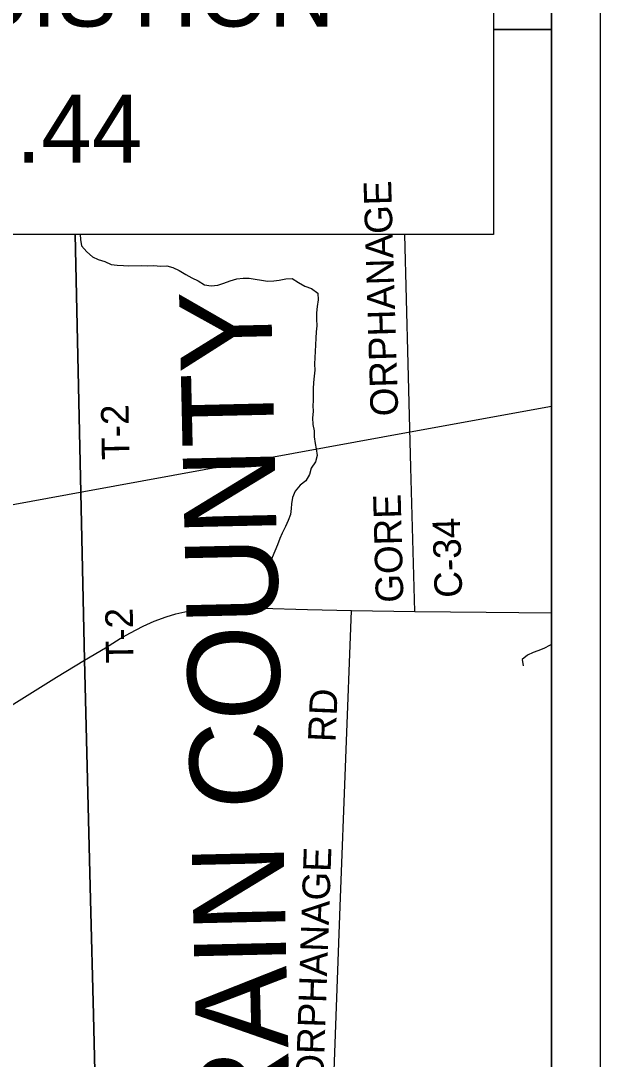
# Model space of a CAD drawing. Extents: x 0 to 34, y 0 to 22.
# Drawn here: x 7.808 to 9, y 17.578 to 19.717 of the extents above; entities that cross this region are included whole.
import ezdxf

# ---------------------------------------------------------------- set-up
doc = ezdxf.new("R2010")
doc.units = 0
for name, color, linetype in [('GM_X_Corporation', 7, 'Continuous'), ('GM_X_County_Road', 7, 'Continuous'), ('GM_X_County_Road_Text', 7, 'Continuous'), ('GM_X_County_Text', 7, 'Continuous'), ('GM_X_Minor_River', 7, 'Continuous'), ('GM_X_Rail_Line', 7, 'Continuous'), ('GM_X_Township_Road', 7, 'Continuous'), ('GM_X_Township_Road_Text', 7, 'Continuous'), ('GM_X_US_Route', 7, 'Continuous'), ('SH_Data', 7, 'Continuous'), ('SH_Text', 7, 'Continuous')]:
    doc.layers.add(name, color=color, linetype=linetype)

msp = doc.modelspace()

# ---------------------------------------------------------------- linework, layer by layer
at = {"layer": 'GM_X_Corporation'}
for points in [[(8.7801, 19.7002), (8.9, 19.6997), (8.9, 20.9), (7.8853, 20.9), (7.8855, 20.8777), (7.8865, 20.8322), (7.8862, 20.7899), (7.8881, 20.7568), (7.8881, 20.7393), (7.8896, 20.6817), (7.8919, 20.5951), (7.8945, 20.502), (7.9008, 20.2877), (7.9013, 20.2705), (7.9044, 19.994), (8.7801, 19.994)], [(7.9196, 19.2769), (7.9387, 18.4008), (7.951, 17.9078), (7.9575, 17.6697), (7.9659, 17.2939), (7.973, 17.0583), (7.9733, 17.0489), (7.9799, 16.8298), (7.992, 16.4534), (8.0153, 15.2273), (8.0262, 14.6555), (8.0297, 14.4963), (8.2922, 14.4944), (8.9, 14.4898), (8.9, 19.6997), (8.7801, 19.7002), (8.7801, 19.2769)]]:
    msp.add_lwpolyline(points, close=True, dxfattribs=at)
for points in [[(8.9, 14.1), (8.9, 20.9)], [(8.0153, 15.2273), (7.992, 16.4534), (7.9799, 16.8298), (7.9733, 17.0489), (7.973, 17.0583), (7.9659, 17.2939), (7.9575, 17.6697), (7.951, 17.9078), (7.9387, 18.4008), (7.9196, 19.2769), (6.5603, 19.2769), (6.5603, 19.994)], [(8.0153, 15.2273), (7.992, 16.4534), (7.9799, 16.8298), (7.9733, 17.0489), (7.973, 17.0583), (7.9659, 17.2939), (7.9575, 17.6697), (7.951, 17.9078), (7.9387, 18.4008), (7.9196, 19.2769), (6.5603, 19.2769), (6.5603, 19.994)], [(8.7801, 19.994), (8.7801, 19.2769), (7.9196, 19.2769), (7.9387, 18.4008), (7.951, 17.9078), (7.9575, 17.6697), (7.9659, 17.2939), (7.973, 17.0583), (7.9733, 17.0489), (7.9799, 16.8298), (7.992, 16.4534), (8.0153, 15.2273)]]:
    msp.add_lwpolyline(points, dxfattribs=at)
at = {"layer": 'GM_X_County_Road'}
for p, q in [((8.7801, 19.6997), (8.9, 19.6992)), ((8.4882, 18.5028), (8.6184, 18.5005))]:
    msp.add_line(p, q, dxfattribs=at)
for points in [[(8.6184, 18.5005), (8.6101, 18.7975), (8.6049, 19.0107), (8.598, 19.2769)], [(8.435, 17.0471), (8.4437, 17.3104), (8.465, 17.8934), (8.4882, 18.5028)]]:
    msp.add_lwpolyline(points, dxfattribs=at)
at = {"layer": 'GM_X_Minor_River'}
for points in [[(7.9299, 19.2769), (7.9303, 19.2665), (7.9327, 19.2536), (7.9431, 19.2412), (7.955, 19.2314), (7.9669, 19.2259), (7.9802, 19.2218), (7.9932, 19.2155), (8.0062, 19.2142), (8.0191, 19.2132), (8.0287, 19.2129), (8.0557, 19.2132), (8.0686, 19.2126), (8.0815, 19.2131), (8.0952, 19.2122), (8.1082, 19.2123), (8.1207, 19.209), (8.1337, 19.2031), (8.1472, 19.1949), (8.1594, 19.1878), (8.1728, 19.1815), (8.1858, 19.1733), (8.1992, 19.1712), (8.2132, 19.1729), (8.2253, 19.1772), (8.2382, 19.1815), (8.2519, 19.1858), (8.2655, 19.1875), (8.2777, 19.1873), (8.2899, 19.1851), (8.3029, 19.1834), (8.3151, 19.1812), (8.328, 19.1818), (8.3394, 19.1834), (8.353, 19.1859), (8.366, 19.1864), (8.3794, 19.1782), (8.3924, 19.1707), (8.4058, 19.166), (8.4188, 19.1562), (8.4193, 19.1426), (8.4172, 19.1288), (8.4158, 19.1155), (8.4164, 19.1026), (8.4165, 19.0889), (8.4151, 19.0768), (8.4145, 19.0635), (8.4143, 19.0498), (8.4137, 19.0365), (8.4127, 19.0235), (8.4117, 19.0102), (8.4126, 18.9977), (8.4116, 18.9855), (8.4099, 18.9722), (8.4092, 18.9593), (8.4094, 18.9471), (8.4091, 18.9346), (8.4085, 18.9247), (8.4094, 18.9125), (8.408, 18.8996), (8.4086, 18.8859), (8.4114, 18.873), (8.4111, 18.8601), (8.4132, 18.8464), (8.4156, 18.8355), (8.4173, 18.8218), (8.414, 18.8088), (8.4054, 18.7962), (8.4014, 18.7828), (8.3943, 18.7698), (8.3822, 18.761)], [(8.3822, 18.761), (8.3721, 18.7483), (8.3665, 18.7353), (8.3648, 18.7224), (8.3637, 18.7129), (8.3624, 18.7003), (8.3579, 18.6881), (8.3524, 18.6759), (8.3453, 18.6621), (8.3405, 18.6507), (8.3357, 18.6377), (8.3301, 18.6247), (8.3246, 18.6121), (8.3217, 18.5984)], [(8.9, 18.4319), (8.8972, 18.431), (8.8843, 18.4244), (8.8718, 18.4197), (8.862, 18.4161), (8.8502, 18.4107), (8.8397, 18.4018), (8.8414, 18.3885)]]:
    msp.add_lwpolyline(points, dxfattribs=at)
at = {"layer": 'GM_X_Rail_Line'}
for points in [[(7.9374, 18.7476), (8.6162, 18.872), (8.9, 18.9239)], [(2.1, 18.3652), (2.4476, 18.3515), (3.7542, 18.2908), (4.7355, 18.2536), (4.912, 18.2502), (5.0326, 18.2535), (5.2097, 18.2563), (5.4881, 18.3005), (6.2957, 18.4383), (6.9068, 18.5576), (7.5368, 18.6745), (7.9374, 18.7476)]]:
    msp.add_lwpolyline(points, dxfattribs=at)
at = {"layer": 'GM_X_Township_Road'}
for p, q in [((7.9249, 19.0421), (7.9198, 19.2769)), ((7.9389, 18.4003), (7.9249, 19.0421))]:
    msp.add_line(p, q, dxfattribs=at)
at = {"layer": 'GM_X_US_Route'}
msp.add_line((8.4882, 18.5028), (8.6184, 18.5005), dxfattribs=at)
for points in [[(7.9389, 18.4003), (7.982, 18.4258), (8.0122, 18.4449), (8.0321, 18.4563), (8.0592, 18.4707), (8.0817, 18.4809), (8.1067, 18.4898), (8.1268, 18.4958), (8.1453, 18.5002), (8.1715, 18.5045), (8.193, 18.5073), (8.2147, 18.5087), (8.2395, 18.5087), (8.3024, 18.5076), (8.3979, 18.5045), (8.4882, 18.5028)], [(8.6184, 18.5005), (8.7651, 18.499), (8.9, 18.4976)], [(5.4163, 18.2283), (5.4371, 18.2285), (5.6077, 18.2299), (6.0537, 18.236), (6.391, 18.2389), (6.9082, 18.2451), (7.1657, 18.2463), (7.3782, 18.2472), (7.5886, 18.2484), (7.6469, 18.2534), (7.6916, 18.2633), (7.7387, 18.2806), (7.7821, 18.3038), (7.8813, 18.3654), (7.9389, 18.4003)]]:
    msp.add_lwpolyline(points, dxfattribs=at)
at = {"layer": 'SH_Data'}
for p, q in [((9, 21), (9, 14)), ((8.9, 20.9), (8.9, 14.1))]:
    msp.add_line(p, q, dxfattribs=at)
at = {"layer": 'SH_Text'}
msp.add_lwpolyline([(6.5603, 19.994), (8.7801, 19.994), (8.7801, 19.2769), (6.5603, 19.2769)], close=True, dxfattribs=at)

# ---------------------------------------------------------------- texts
at = {"layer": 'GM_X_County_Road_Text'}
for s, rotation, p in [('ORPHANAGE', 91.7493, (8.5844, 18.9036)), ('GORE', 91.5142, (8.5952, 18.5195)), ('C-34', 91.7153, (8.7162, 18.5297)), ('RD', 87.5314, (8.4552, 18.231)), ('ORPHANAGE', 88.0322, (8.4302, 17.5291))]:
    msp.add_text(s, height=0.05682, rotation=rotation, dxfattribs=at).set_placement(p)
at = {"layer": 'GM_X_County_Text'}
msp.add_text('LORAIN COUNTY', height=0.189394, rotation=91.3059, dxfattribs=at).set_placement((8.3699, 17.082))
at = {"layer": 'GM_X_Township_Road_Text'}
for rotation, p in [(91.1215, (8.0313, 18.8137)), (90.9543, (8.0398, 18.3945))]:
    msp.add_text('T-2', height=0.05682, rotation=rotation, dxfattribs=at).set_placement(p)
at = {"layer": 'SH_Text'}
for s, p in [('END ACQUISTION', (6.8413, 19.7054)), ('SLM 2.44', (7.2565, 19.4254))]:
    msp.add_text(s, height=0.14, dxfattribs=at).set_placement(p)

doc.saveas('drawing.dxf')
